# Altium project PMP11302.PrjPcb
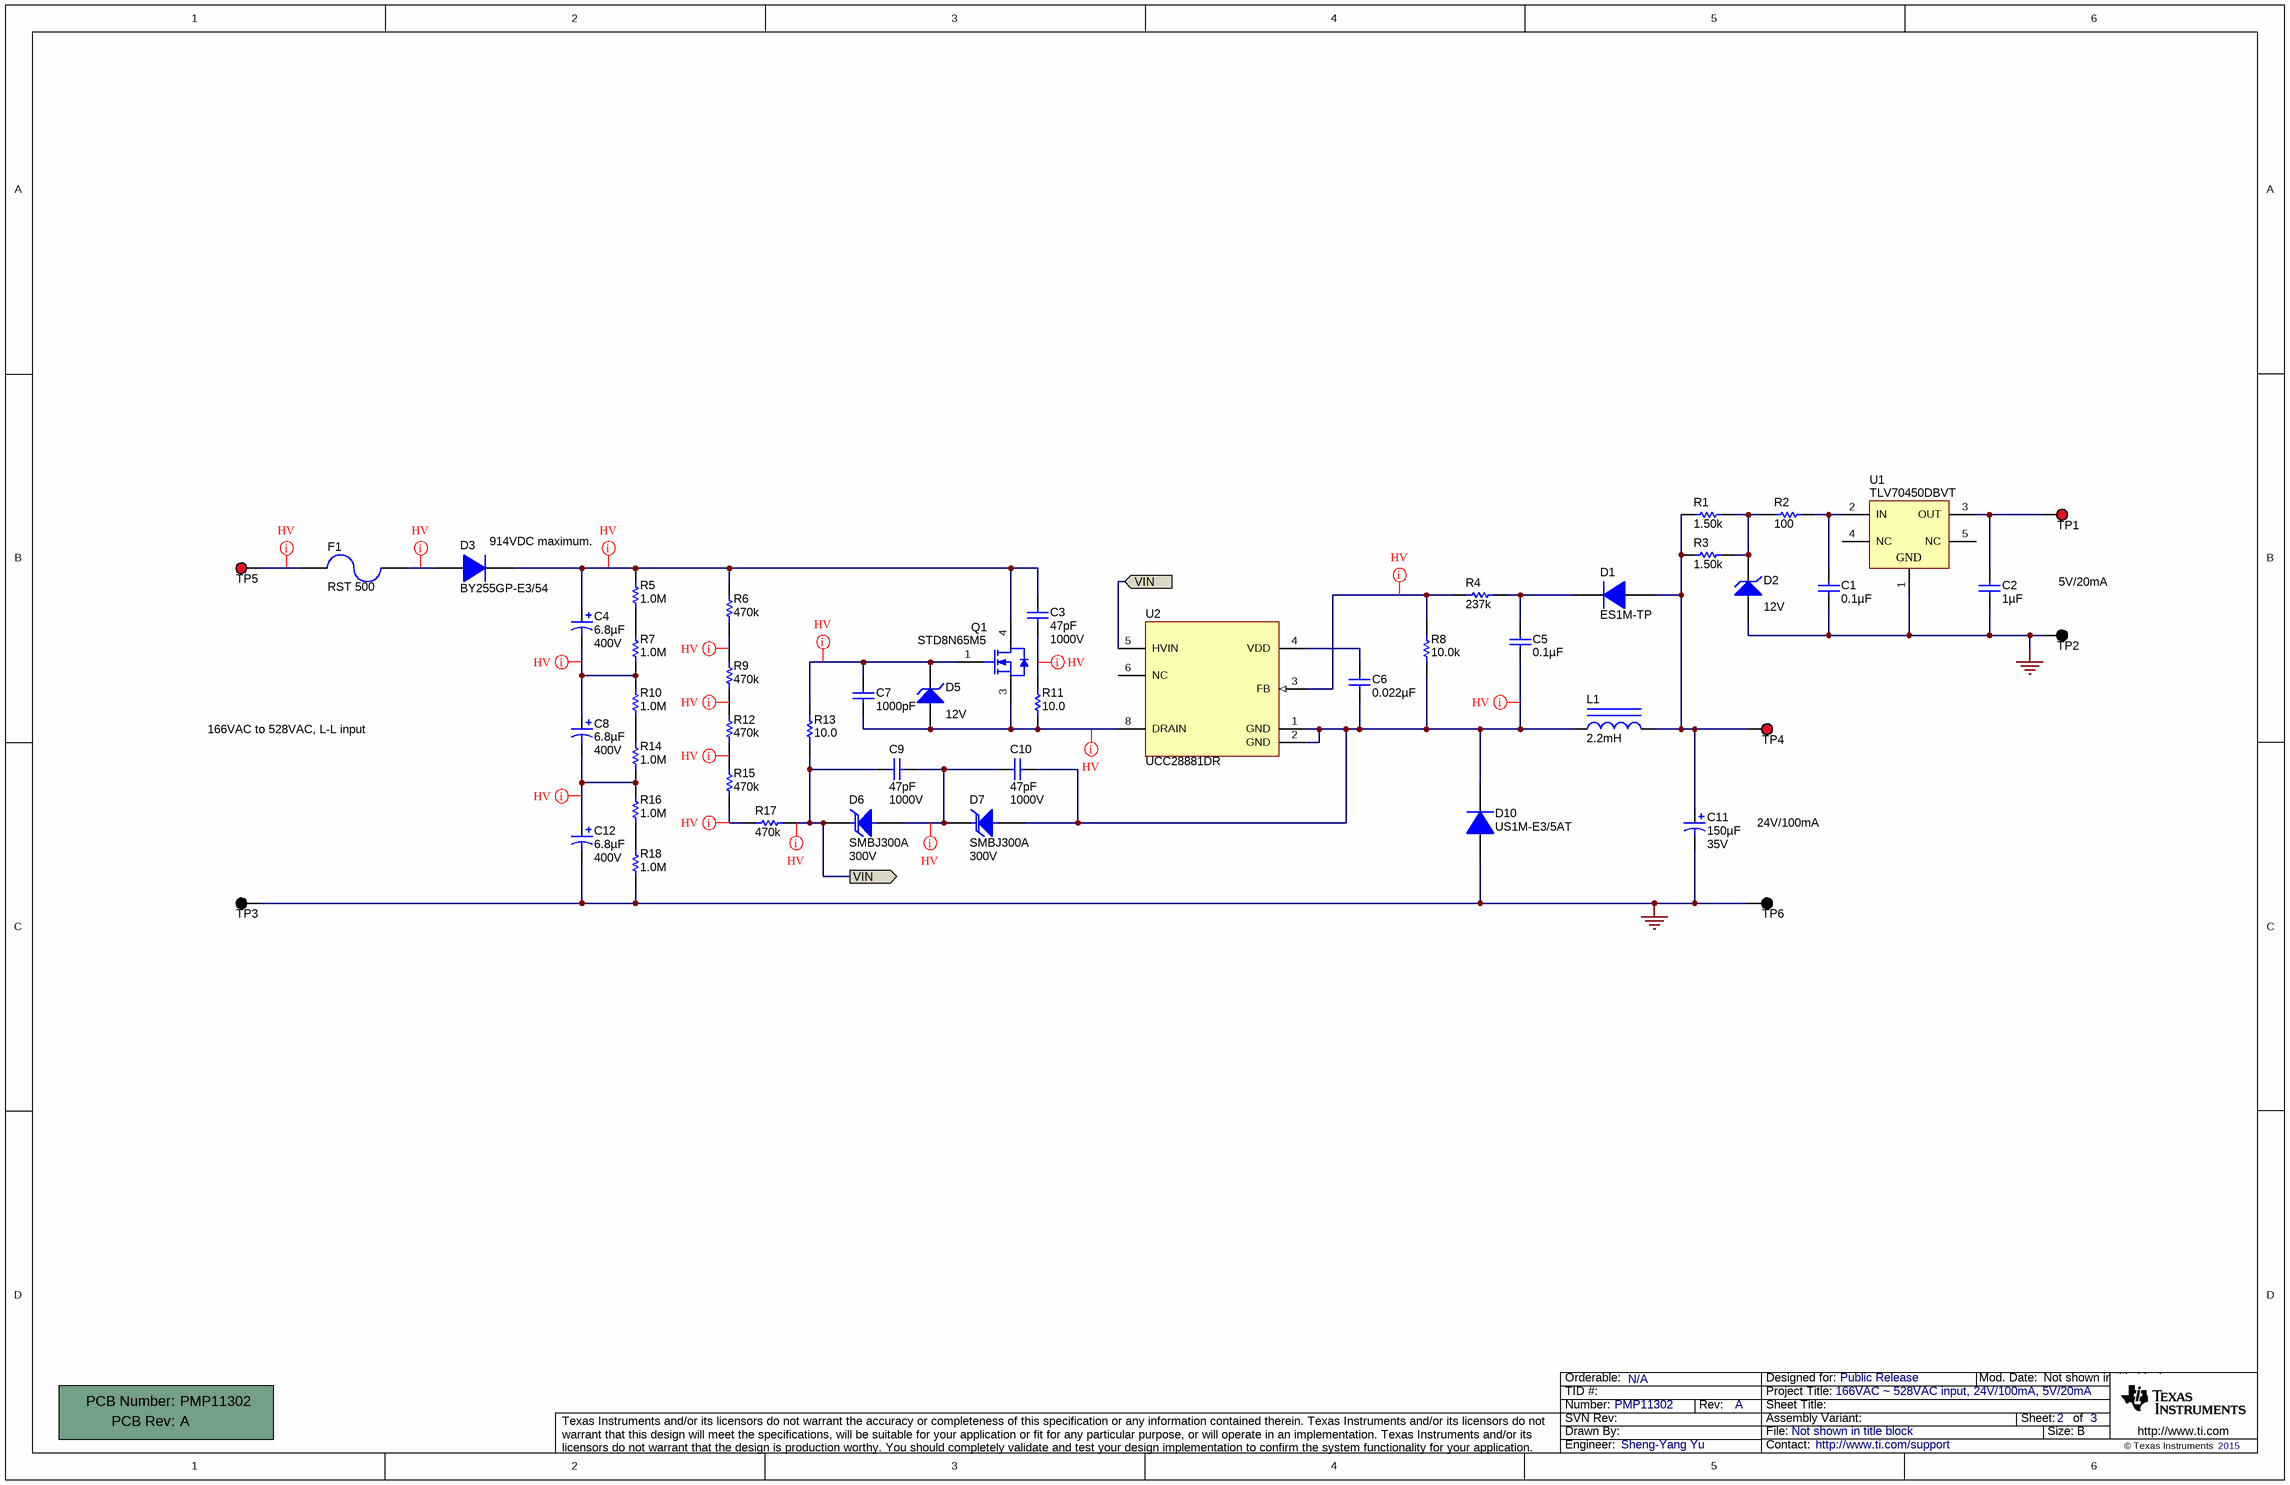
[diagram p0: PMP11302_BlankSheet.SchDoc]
CopyrightYear: 2015; EVM_Orderable: N/A; PCB_Layout: Sheng-Yang Yu; PCB_Rev: A; PRJ_Customer: Public Release; PRJ_Engineer: Sheng-Yang Yu; PRJ_Number: PMP11302; PRJ_Title: 166VAC ~ 528VAC input, 24V/100mA, 5V/20mA; SCH_Rev: A; TechSupport: http://www.ti.com/support
1 sheet, 49 parts. Net scope: flat (ports and power ports of the same name join across sheets).
Board file: PMP11302_TID.PcbDoc

## Sheet PMP11302_BlankSheet.SchDoc
size 431 x 279 mm; Date: Not shown in title block; ApprovedBy: Not shown in title block; CheckedBy: Not shown in title block; Author: Not shown in title block; CompanyName: Not shown in title block; Engineer: Not shown in title block; Organization: Not shown in title block; Address1: Not shown in title block; Address2: Not shown in title block; Address3: Not shown in title block; Address4: Not shown in title block; DocumentNumber: 1; Revision: Use project parameter SCH_Rev; SheetNumber: 2; SheetTotal: 3; PageSetup: Record=PageOptions¦CenterHorizontal=True¦CenterVertical=True¦PrintScale=1.00¦XCorrection=1.00¦YCorrection=1.00¦PrintKind=0¦BorderSize=5000000¦LeftOffset=0¦BottomOffset=0¦Orientation=2¦PaperLength=1000¦PaperWidth=1000¦Scale=100¦PaperSource=15¦PrintQuality=600¦MediaType=1¦DitherType=10¦PaperKind=Letter¦PrintScaleMode=1

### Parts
!PCB1  Printed Circuit Board  (value not drawn)  (mechanical)
C1  ValueDisplayed: 0.1µF  [0603]  (hidden comment: 06033C104JAT2A)
C2  ValueDisplayed: 1µF  [0603]  (hidden comment: C0603C105K4PACTU)
C3  ValueDisplayed: 47pF  Value2: 1000V  [1206]  (hidden comment: VJ1206A470JXGAT5Z)
C4  ValueDisplayed: 6.8µF  Value2: 400V  [CAPPRD350W60D800H1100]  (hidden comment: 400AX6R8M8x11)
C5  ValueDisplayed: 0.1µF  [1206]  (hidden comment: 12065C104JAT2A)
C6  ValueDisplayed: 0.022µF  [1206]  (hidden comment: 12065C223KAT2A)
C7  ValueDisplayed: 1000pF  [0603]  (hidden comment: 06035A102KAT2A)
C8  ValueDisplayed: 6.8µF  Value2: 400V  [CAPPRD350W60D800H1100]  (hidden comment: 400AX6R8M8x11)
C9  ValueDisplayed: 47pF  Value2: 1000V  [1206]  (hidden comment: GRM31A7U3A470JW31D)
C10  ValueDisplayed: 47pF  Value2: 1000V  [1206]  (hidden comment: GRM31A7U3A470JW31D)
C11  ValueDisplayed: 150µF  Value2: 35V  [HE_800x1150]  (hidden comment: UPW1V151MPD)
C12  ValueDisplayed: 6.8µF  Value2: 400V  [CAPPRD350W60D800H1100]  (hidden comment: 400AX6R8M8x11)
D1  ES1M-TP  [SMA]
D2  value 12V  [SMA]  (hidden comment: 1SMA5927BT3G)
D3  BY255GP-E3/54  [DO-201AD]
D5  value 12V  [SMA]  (hidden comment: 1SMA5927BT3G)
D6  SMBJ300A  value 300V  [SMB]
D7  SMBJ300A  value 300V  [SMB]
D10  US1M-E3/5AT  [SMA]
F1  RST 500  [Fuse_RST]
L1  ValueDisplayed: 2.2mH  [WE-TI_8055]  (hidden comment: 744741222)
Q1  STD8N65M5  [DPAK]
R1  ValueDisplayed: 1.50k  [1206]  (hidden comment: CRCW12061K50FKEA)
R2  ValueDisplayed: 100  [1206]  (hidden comment: CRCW1206100RFKEA)
R3  ValueDisplayed: 1.50k  [1206]  (hidden comment: CRCW12061K50FKEA)
R4  ValueDisplayed: 237k  [0603]  (hidden comment: RC0603FR-07237KL)
R5  ValueDisplayed: 1.0M  [0603]  (hidden comment: CRCW06031M00JNEA)
R6  ValueDisplayed: 470k  [0805_HV]  (hidden comment: CRCW0805470KJNEA)
R7  ValueDisplayed: 1.0M  [0603]  (hidden comment: CRCW06031M00JNEA)
R8  value 10.0k  [0603]  (hidden comment: CRCW060310K0FKEA)
R9  ValueDisplayed: 470k  [0805_HV]  (hidden comment: CRCW0805470KJNEA)
R10  ValueDisplayed: 1.0M  [0603]  (hidden comment: CRCW06031M00JNEA)
R11  ValueDisplayed: 10.0  [1206]  (hidden comment: CRCW120610R0FKEA)
R12  ValueDisplayed: 470k  [0805_HV]  (hidden comment: CRCW0805470KJNEA)
R13  ValueDisplayed: 10.0  [1206]  (hidden comment: CRCW120610R0FKEA)
R14  ValueDisplayed: 1.0M  [0603]  (hidden comment: CRCW06031M00JNEA)
R15  ValueDisplayed: 470k  [0805_HV]  (hidden comment: CRCW0805470KJNEA)
R16  ValueDisplayed: 1.0M  [0603]  (hidden comment: CRCW06031M00JNEA)
R17  ValueDisplayed: 470k  [0805_HV]  (hidden comment: CRCW0805470KJNEA)
R18  ValueDisplayed: 1.0M  [0603]  (hidden comment: CRCW06031M00JNEA)
TP1  5000  [Keystone5000]  (value not drawn)
TP2  5001  [Keystone5001]  (value not drawn)
TP3  5001  [Keystone5001]  (value not drawn)
TP4  5000  [Keystone5000]  (value not drawn)
TP5  5000  [Keystone5000]  (value not drawn)
TP6  5001  [Keystone5001]  (value not drawn)
U1  TLV70450DBVT  [DBV0005A_N]
U2  UCC28881DR  [D0007A_N]

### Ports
VIN (in), VIN (out)

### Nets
GND: C1.2 C2.2 C11.2(-) C12.2(-) D2.2(A) D10.2(A) R18.1 TP2.1 TP3.1 TP6.1 U1.1(GND)
VIN: C9.1 D6.1(K) R13.1 R17.1 U2.5(HVIN) ; port VIN
NetC1_1: C1.1 R2.2 U1.2(IN)
NetC2_1: C2.1 TP1.1 U1.3(OUT)
NetC3_1: C3.1 C4.1(+) D3.1(K) Q1.4(D) R5.2 R6.2
NetC3_2: C3.2 R11.2
NetC4_2: C4.2(-) C8.1(+) R7.1 R10.2
NetC5_1: C5.1 D1.1(K) R4.2
NetC5_2: C5.2 C6.2 C10.2 D7.2(A) D10.1(K) L1.1 R8.1 U2.1(GND) U2.2(GND)
NetC6_1: C6.1 U2.4(VDD)
NetC7_1: C7.1 D5.1(K) Q1.1(G) R13.2
NetC7_2: C7.2 D5.2(A) Q1.3(S) R11.1 U2.8(DRAIN)
NetC8_2: C8.2(-) C12.1(+) R14.1 R16.2
NetC9_2: C9.2 C10.1 D6.2(A) D7.1(K)
NetC11_1: C11.1(+) D1.2(A) L1.2 R1.1 R3.1 TP4.1
NetD2_1: D2.1(K) R1.2 R2.1 R3.2
NetD3_2: D3.2(A) F1.1
NetF1_2: F1.2 TP5.1
NetR4_1: R4.1 R8.2 U2.3(FB)
NetR5_1: R5.1 R7.2
NetR6_1: R6.1 R9.2
NetR9_1: R9.1 R12.2
NetR10_1: R10.1 R14.2
NetR12_1: R12.1 R15.2
NetR15_1: R15.1 R17.2
NetR16_1: R16.1 R18.2

Not connected (* = marked no-connect by the designer): U1 4(NC) 5(NC); U2 6(NC)

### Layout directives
net class HV: NetC3_1, NetC3_2, NetC4_2, NetC5_2, NetC7_1, NetC7_2, NetC8_2, NetC9_2, NetD3_2, NetF1_2, NetR4_1, NetR6_1, NetR9_1, NetR12_1, NetR15_1, VIN

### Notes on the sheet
- (near D3) 914VDC maximum.
- 5V/20mA
- 166VAC to 528VAC, L-L input
- 24V/100mA

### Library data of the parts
!PCB1 = PCB: Manufacturer: Any; PartNumber: PMP11302; SymbolCreator: a0412235
C1 = 06033C104JAT2A: CAP, CERM, 0.1 µF, 25 V, +/- 5%, X7R, 0603; Manufacturer: AVX; Polarized: N; CompType: Capacitor; Value: 0.1uF; U/M: EA; Cap_F: 0.0000001; Tolerance_%: 5; ESR_ohm: 0.05; Value1: 0.05 ohm; VDC_V: 25; Value2: 25V; TaMin_C: -55; TaMax_C: 125
C2 = C0603C105K4PACTU: CAP, CERM, 1 µF, 16 V, +/- 10%, X5R, 0603; Manufacturer: Kemet; Polarized: N; CompType: Capacitor; Value: 1uF; U/M: EA; Cap_F: 0.000001; Tolerance_%: 10; Value1: Unknown; VDC_V: 16; Value2: 16V; TaMin_C: -55; TaMax_C: 85
C3 = VJ1206A470JXGAT5Z: CAP, CERM, 47 pF, 1000 V, +/- 5%, C0G/NP0, 1206; Manufacturer: Vishay-Vitramon; Polarized: N; CompType: Capacitor; Value: 47pF; U/M: EA; Cap_F: 0.000000000047; Tolerance_%: 5; Value1: Unknown; VDC_V: 1000; TaMin_C: -55; TaMax_C: 125
C4 C8 C12 = 400AX6R8M8x11: CAP, AL, 6.8 µF, 400 V, +/- 20%, TH; Manufacturer: Rubycon; Polarized: Y; CompType: Capacitor; Value: 6.8uF; U/M: EA; Cap_F: 0.0000068; Tolerance_%: 20; Value1: Unknown; VDC_V: 400; TaMin_C: -40; TaMax_C: 105; Cap_Case: 8x11
C5 = 12065C104JAT2A: CAP, CERM, 0.1uF, 50V, +/-5%, X7R, 1206; Manufacturer: AVX; Polarized: N; CompType: Capacitor; U/M: EA; Cap_F: 0.0000001; Tolerance_%: 5; ESR_Ohm: 0.037; Value1: 0.037 ohm; VDC_V: 50; TaMin_C: -55; TaMax_C: 125
C6 = 12065C223KAT2A: CAP, CERM, 0.022uF, 50V, +/-10%, X7R, 1206; Manufacturer: AVX; Polarized: N; CompType: Capacitor; U/M: EA; Cap_F: 0.000000022; Tolerance_%: 10; ESR_Ohm: 0.079; Value1: 0.079 ohm; VDC_V: 50; TaMin_C: -55; TaMax_C: 125
C7 = 06035A102KAT2A: CAP, CERM, 1000 pF, 50 V, +/- 10%, C0G/NP0, 0603; Manufacturer: AVX; Polarized: N; CompType: Capacitor; Value: 1000pF; U/M: EA; Cap_F: 0.000000001; Tolerance_%: 10; ESR_ohm: 0.048; Value1: 0.048 ohm; VDC_V: 50; Value2: 50V; TaMin_C: -55; TaMax_C: 125
C9 C10 = GRM31A7U3A470JW31D: CAP, CERM, 47 pF, 1000 V, +/- 5%, U2J, 1206; Manufacturer: MuRata; Polarized: N; CompType: Capacitor; Value: 47pF; U/M: EA; Cap_F: 0.000000000047; Tolerance_%: 5; Value1: Unknown; VDC_V: 1000; TaMin_C: -55; TaMax_C: 125
C11 = UHE1H101MPD: CAP ALUM 150UF 35V 20% RADIAL; Manufacturer: Nichicon; Polarized: Y; CompType: Capacitor; U/M: EA; Cap_F: 0.0001; Tolerance_%: 20; Value1: 0.17 ohm; VDC_V: 35; ESR_ohm: 0.17; IRMS_A: 0.555; TaMin_C: -40; TaMax_C: 105; Cap_Case: 8x11.5
D1 = ES1D-13-F: DIODE GEN PURP 1KV 1A DO214AC; Manufacturer: Micro Commercial Co; Value: 1000V; U/M: EA; Io_A: 1; Vr_V: 800; TJmax_C: 150; RJC_CperW: 25; Type: Ultrafast
D2 D5 = 1SMA5927BT3G: Diode, Zener, 12 V, 1.5 W, SMA; Manufacturer: ON Semiconductor; SymbolCreator: a0412235; U/M: EA; Power_W: 1.5; Vz_V: 12; Value1: 1.5W; RJA_CperW: 250
D3 = BY255GP-E3/54: Diode, P-N, 1300 V, 3 A, TH; Manufacturer: Vishay-Semiconductor; U/M: EA; Vf_V: 1.1; Value: 1300V; Value1: 3A; Value2: 1.1V; Io_A: 3; Vr_V: 1300; TJmax_C: 175; RJC_CperW: 20; AEC Category: Q101
D6 D7 = SMBJ30A-13-F: TVS DIODE 300VWM 486VC SMB; Manufacturer: Littelfuse Inc.; U/M: EA; Power_W: 5; Vr_V: 300; Value1: 5W; AEC Category: Q101
D10 = US1K-13-F: DIODE GEN PURP 1KV 1A DO214AC; Manufacturer: Vishay; U/M: EA; Vf_V: 1.7; Value: 1000V; Value2: 1.7V; Io_A: 1; Vr_V: 1000; TJmax_C: 150; Type: Fast Rectifier
F1 = RST 500: Fuse, 0.5 A, 250 V, TH; Manufacturer: Bel Fuse; U/M: EA; OpeningTime_100%_min: 1; OpeningTime_200%_max: 120; VDC_V: 250; Irating_A: 0.5; Rtyp_Ohm: 0.18; MeltingTyp: 1.7; Vdrop: 0.114; Soldering_Wave_MaxTemp_C: 260; Soldering_Wave_MaxTime_s: 10
L1 = 744741101: FIXED IND 2.2MH 210MA 11 OHM TH; Manufacturer: Wurth Elektronik; CompType: Inductor; Material: Ferrite
Q1 = STD13NM60N: MOSFET N-CH 650V 7A DPAK; Manufacturer: STMicroelectronics; Alternate Manufacturer: None; U/M: EA; ChType: N; VdsMax_V: 650; Rdson45_ohm: 0.36; Value2: 30 nC; QgTyp_nC: 30; Vgs_V: 4; IdsMax_A: 11; AEC Category: Q101
R1 R3 = CRCW12061K50FKEA: RES, 1.50 k, 1%, 0.25 W, 1206; Manufacturer: Vishay-Dale; CompType: Resistor; Value: 1.50k; Res_ohm: 1500; Value_Code: 1k50; Tolerance_%: 1; Power_W: 0.25; Value2: 0.25W; VDC_V: 200; TempCo: 100 ppm/C; EIA_Code: E96; U/M: EA
R2 = CRCW1206100RFKEA: RES, 100, 1%, 0.25 W, 1206; Manufacturer: Vishay-Dale; CompType: Resistor; Value: 100; Value_Code: 100R; Tolerance_%: 1; Power_W: 0.25; Value2: 0.25W; VDC_V: 200; TempCo: 100 ppm/C; EIA_Code: E96; U/M: EA
R4 = RC0603FR-07237KL: RES, 237 k, 1%, 0.1 W, 0603; Manufacturer: Yageo America; CompType: Resistor; Value: 237k; Res_ohm: 237000; Tolerance_%: 1; Power_W: 0.1; Value2: 0.1W; VDC_V: 150; TempCo: 200 ppm/C; EIA_Code: E96; U/M: EA
R5 R7 R10 R14 R16 R18 = CRCW06031M00JNEA: RES, 1.0 M, 5%, 0.1 W, 0603; Manufacturer: Vishay-Dale; CompType: Resistor; Value: 1.0Meg; Res_ohm: 1000000; Value_Code: 1M00; Tolerance_%: 5; Power_W: 0.1; Value2: 0.1W; VDC_V: 75; TempCo: 200 ppm/C; EIA_Code: E24; U/M: EA
R6 R9 R12 R15 R17 = CRCW0805470KJNEA: RES, 470 k, 5%, 0.125 W, 0805; Manufacturer: Vishay-Dale; CompType: Resistor; Value: 470k; Res_ohm: 470000; Tolerance_%: 5; Power_W: 0.125; Value2: 0.125W; VDC_V: 150; TempCo: 200 ppm/C; EIA_Code: E24; U/M: EA; AEC Category: Q200
R8 = CRCW060310K0FKEA: RES, 10.0k ohm, 1%, 0.1W, 0603; Manufacturer: Vishay-Dale; CompType: Resistor; Res_ohm: 10000; Value_Code: 10k0; Tolerance_%: 1; Power_W: 0.1; VDC_V: 75; TempCo: 100 ppm/C; EIA_Code: E96; U/M: EA
R11 R13 = CRCW120610R0FKEA: RES, 10.0, 1%, 0.25 W, 1206; Manufacturer: Vishay-Dale; CompType: Resistor; Value: 10.0; Res_ohm: 10; Value_Code: 10R0; Tolerance_%: 1; Power_W: 0.25; Value2: 0.25W; VDC_V: 200; TempCo: 100 ppm/C; EIA_Code: E96; U/M: EA
TP1 TP4 TP5 = 5000: Test Point, Miniature, Red, TH; Manufacturer: Keystone; CompType: Test Point Loop; U/M: EA
TP2 TP3 TP6 = 5001: Test Point, Miniature, Black, TH; Manufacturer: Keystone; CompType: Test Point Loop; U/M: EA
U1 = TLV70450DBVT: Single Output LDO, 150 mA, Fixed 5 V Output, 2.5 to 24 V Input, with Ultra-Low IQ, 5-pin SOT-23 (DBV), -40 to 125 degC, Green (RoHS & no Sb/Br); Manufacturer: Texas Instruments; Alternate Manufacturer: None; Alternate PartNumber: Equivalent; Accuracy(%): 2; Fixed Output Options(V): 5; Iout(Max)(A): 0.15; Iq(Typ)(mA): 0.003; SubFamily: Single Channel LDO; Vdo(Typ)(mV): 400; Vin(Max)(V): 24; Vin(Min)(V): 2.5
U2 = UCC28881DR: 700-V Lowest Quiescent Current Off-Line Switcher, D0007A; Manufacturer: Texas Instruments; SymbolCreator: a0411947; CompType: IC; U/M: EA

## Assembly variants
001: not fitted C7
